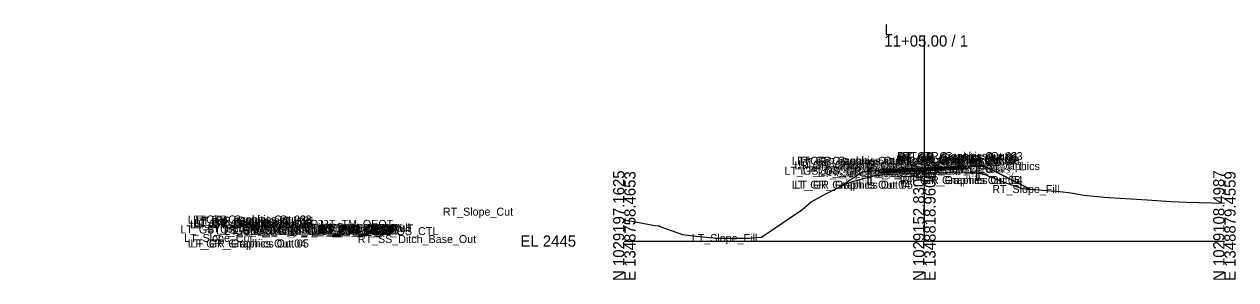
# Model space of a CAD drawing. Extents: x -26 to 1453, y -10 to 4527.
# Drawn here: x 1150 to 1452.8, y -9.7 to 54.3 of the extents above; entities that cross this region are included whole.
import ezdxf

# ---------------------------------------------------------------- set-up
doc = ezdxf.new("R2010")
doc.units = 0
for name, color, linetype in [('Default', 7, 'Continuous'), ('Exist Cross Section Cell', 7, 'Continuous'), ('Exist XS Center Line Elevation Label', 7, 'Continuous'), ('Exist XS Ground Line', 7, 'Continuous'), ('Old_Level_63', 7, 'Continuous'), ('Prop CMT Guardrail Graphics', 7, 'Continuous'), ('Prop CMT Pvmt Course 1', 7, 'Continuous'), ('Prop CMT Pvmt Course 2', 7, 'Continuous'), ('Prop CMT Pvmt Course 3', 7, 'Continuous'), ('Prop CMT Pvmt Surface', 7, 'Continuous'), ('Prop CMT Pvmt Surface Overlay', 7, 'Continuous'), ('Prop CMT Pvmt Surface Shoulder', 7, 'Continuous'), ('Prop CMT Shld Paved Course 1', 7, 'Continuous'), ('Prop CMT Shld Paved Course 2', 7, 'Continuous'), ('Prop CMT Shld Paved Course 3', 7, 'Continuous'), ('Prop CMT Slope Grass', 7, 'Continuous'), ('Prop CMT Subgrade Earthwork', 7, 'Continuous'), ('Prop XS Earthwork Shape', 7, 'Continuous'), ('Prop XS EOT Tick Mark', 7, 'Continuous'), ('Prop XS SE Text', 7, 'Continuous'), ('Prop XS Side Slope Text', 7, 'Continuous')]:
    doc.layers.add(name, color=color, linetype=linetype)

msp = doc.modelspace()

# ---------------------------------------------------------------- linework, layer by layer
at = {"layer": 'Exist Cross Section Cell'}
for p, q in [((1375, 0), (1375, 51.49)), ((1300, 0), (1375, 0)), ((1375, 0), (1450, 0))]:
    msp.add_line(p, q, dxfattribs=at)
at = {"layer": 'Exist XS Ground Line'}
msp.add_lwpolyline([(1300, 5.32), (1303.73, 4.67), (1307.54, 3.94), (1308.46, 3.79), (1308.77, 3.81), (1309.11, 3.59), (1314.51, 1.66), (1317.96, 1.27), (1323.09, 0.76), (1330.64, 0.75), (1334.29, 0.96), (1344.35, 7.82), (1346.72, 9.86), (1350.36, 11.85), (1354.94, 14.05), (1356.27, 14.69), (1357.04, 14.91), (1362.25, 16.35), (1365.44, 16.65), (1367.07, 16.77), (1368.72, 16.85), (1375, 17.08), (1376.08, 17.12), (1378.11, 17.11), (1385.47, 17.16), (1387.13, 17.06), (1389.45, 16.93), (1395.37, 14.58), (1399.46, 13.14), (1403.47, 12.8), (1408.88, 12.38), (1411.63, 12.09), (1414.85, 11.52), (1419.92, 10.98), (1430.69, 10.29), (1436.67, 9.87), (1440.4, 9.74), (1450, 9.5)], dxfattribs=at)
at = {"layer": 'Prop CMT Guardrail Graphics'}
for points in [[(1388.67, 21.27), (1387.34, 21.27), (1387.07, 20.98)], [(1388.67, 15.27), (1388.67, 21.27)], [(1360.98, 14.11), (1360.98, 20.11)], [(1360.98, 20.11), (1362.31, 20.11), (1362.58, 19.81)], [(1362.58, 19.23), (1362.31, 18.94), (1361.64, 18.94)], [(1361.64, 18.94), (1361.64, 14.11)], [(1362.58, 19.81), (1362.31, 19.52)], [(1362.31, 19.52), (1362.58, 19.23)], [(1387.07, 20.98), (1387.34, 20.69)], [(1387.34, 20.69), (1387.07, 20.4)], [(1387.07, 20.4), (1387.34, 20.11), (1388.01, 20.11)], [(1388.01, 20.11), (1388.01, 15.27)], [(1388.01, 15.27), (1388.67, 15.27)], [(1361.64, 14.11), (1360.98, 14.11)]]:
    msp.add_lwpolyline(points, dxfattribs=at)
at = {"layer": 'Prop CMT Pvmt Course 1'}
for points in [[(1374.96, 18.3), (1364.96, 17.8)], [(1374.96, 18.3), (1384.96, 18.8)], [(1384.96, 18.55), (1374.96, 18.05)], [(1374.96, 18.17), (1374.96, 18.3)], [(1374.96, 18.17), (1374.96, 18.3)], [(1384.96, 18.8), (1384.96, 18.55)], [(1364.96, 17.55), (1374.96, 18.05)], [(1364.96, 17.8), (1364.96, 17.55)], [(1374.96, 18.05), (1374.96, 18.17), (1374.96, 18.17)], [(1374.96, 18.05), (1374.96, 18.17), (1374.96, 18.17)]]:
    msp.add_lwpolyline(points, dxfattribs=at)
at = {"layer": 'Prop CMT Pvmt Course 2'}
for points in [[(1374.96, 18.05), (1384.96, 18.55)], [(1384.96, 18.3), (1374.96, 17.8)], [(1384.96, 18.55), (1384.96, 18.3)], [(1374.96, 18.05), (1364.96, 17.55)], [(1364.96, 17.3), (1374.96, 17.8)], [(1364.96, 17.55), (1364.96, 17.3)], [(1374.96, 17.8), (1374.96, 18.05)], [(1374.96, 17.8), (1374.96, 18.05)]]:
    msp.add_lwpolyline(points, dxfattribs=at)
at = {"layer": 'Prop CMT Pvmt Course 3'}
for points in [[(1374.96, 17.8), (1384.96, 18.3)], [(1384.96, 18.3), (1384.96, 18.05)], [(1374.96, 17.8), (1364.96, 17.3)], [(1364.96, 17.05), (1374.96, 17.55)], [(1364.96, 17.3), (1364.96, 17.05)], [(1384.96, 18.05), (1374.96, 17.55)], [(1374.96, 17.55), (1374.96, 17.8)], [(1374.96, 17.55), (1374.96, 17.8)]]:
    msp.add_lwpolyline(points, dxfattribs=at)
at = {"layer": 'Prop CMT Pvmt Surface'}
for points in [[(1374.96, 18.3), (1364.96, 17.8)], [(1374.96, 18.3), (1384.96, 18.8)]]:
    msp.add_lwpolyline(points, dxfattribs=at)
at = {"layer": 'Prop CMT Pvmt Surface Overlay'}
for points in [[(1374.96, 18.3), (1364.96, 17.8)], [(1374.96, 18.3), (1384.96, 18.8)]]:
    msp.add_lwpolyline(points, dxfattribs=at)
at = {"layer": 'Prop CMT Pvmt Surface Shoulder'}
for points in [[(1384.96, 18.8), (1384.96, 18.8)], [(1364.96, 17.8), (1364.96, 17.8)]]:
    msp.add_lwpolyline(points, dxfattribs=at)
at = {"layer": 'Prop CMT Shld Paved Course 1'}
for points in [[(1384.96, 18.8), (1384.96, 18.8), (1385.2, 18.56)], [(1384.96, 18.55), (1384.96, 18.8)], [(1385.2, 18.56), (1384.96, 18.55)], [(1364.96, 17.8), (1364.96, 17.8), (1364.7, 17.53)], [(1364.7, 17.53), (1364.96, 17.55)], [(1364.96, 17.55), (1364.96, 17.8)]]:
    msp.add_lwpolyline(points, dxfattribs=at)
at = {"layer": 'Prop CMT Shld Paved Course 2'}
for points in [[(1384.96, 18.55), (1385.2, 18.56), (1385.43, 18.32)], [(1384.96, 18.3), (1384.96, 18.55)], [(1385.43, 18.32), (1384.96, 18.3)], [(1364.96, 17.55), (1364.7, 17.53), (1364.43, 17.27)], [(1364.43, 17.27), (1364.96, 17.3)], [(1364.96, 17.3), (1364.96, 17.55)]]:
    msp.add_lwpolyline(points, dxfattribs=at)
at = {"layer": 'Prop CMT Shld Paved Course 3'}
for points in [[(1384.96, 18.3), (1385.43, 18.32)], [(1384.96, 18.05), (1384.96, 18.3)], [(1385.43, 18.32), (1385.43, 18.32)], [(1385.43, 18.32), (1385.67, 18.08)], [(1364.43, 17.27), (1364.17, 17.01)], [(1364.17, 17.01), (1364.96, 17.05)], [(1364.96, 17.3), (1364.43, 17.27)], [(1364.43, 17.27), (1364.43, 17.27)], [(1364.96, 17.05), (1364.96, 17.3)], [(1385.67, 18.08), (1384.96, 18.05)]]:
    msp.add_lwpolyline(points, dxfattribs=at)
at = {"layer": 'Prop CMT Slope Grass'}
for points in [[(1384.96, 18.8), (1387.07, 18.77)], [(1387.07, 18.77), (1390.07, 18.74)], [(1390.07, 18.74), (1401.65, 12.95)], [(1359.58, 17.37), (1353.75, 13.48)], [(1362.58, 17.61), (1359.58, 17.37)], [(1364.96, 17.8), (1362.58, 17.61)]]:
    msp.add_lwpolyline(points, dxfattribs=at)
at = {"layer": 'Prop CMT Subgrade Earthwork'}
for points in [[(1385.67, 18.08), (1386.37, 18.78)], [(1364.17, 17.01), (1363.5, 17.68)], [(1364.96, 17.05), (1364.17, 17.01)], [(1374.96, 17.55), (1364.96, 17.05)], [(1374.96, 17.55), (1384.96, 18.05)], [(1384.96, 18.05), (1385.67, 18.08)]]:
    msp.add_lwpolyline(points, dxfattribs=at)
at = {"layer": 'Prop XS Earthwork Shape'}
for points in [[(1399.46, 13.14), (1401.65, 12.95), (1390.07, 18.74), (1387.07, 18.77), (1386.37, 18.78), (1385.67, 18.08), (1384.96, 18.05), (1374.96, 17.55), (1364.96, 17.05), (1364.17, 17.01), (1363.5, 17.68), (1362.58, 17.61), (1359.58, 17.37), (1353.75, 13.48), (1354.94, 14.05), (1356.27, 14.69), (1357.04, 14.91), (1362.25, 16.35), (1365.44, 16.65), (1367.07, 16.77), (1368.72, 16.85), (1375, 17.08), (1376.08, 17.12), (1378.11, 17.11), (1385.47, 17.16), (1387.13, 17.06), (1389.45, 16.93), (1395.37, 14.58)], [(1362.58, 17.61), (1359.58, 17.37), (1353.75, 13.48), (1354.94, 14.05), (1356.27, 14.69), (1357.04, 14.91), (1362.25, 16.35), (1365.44, 16.65), (1367.07, 16.77), (1368.72, 16.85), (1375, 17.08), (1376.08, 17.12), (1378.11, 17.11), (1385.47, 17.16), (1387.13, 17.06), (1389.45, 16.93), (1395.37, 14.58), (1399.46, 13.14), (1401.65, 12.95), (1390.07, 18.74), (1387.07, 18.77), (1386.37, 18.78), (1385.67, 18.08), (1384.96, 18.05), (1374.96, 17.55), (1364.96, 17.05), (1364.17, 17.01), (1363.5, 17.68)]]:
    msp.add_lwpolyline(points, close=True, dxfattribs=at)
at = {"layer": 'Prop XS EOT Tick Mark'}
for points in [[(1364.96, 17.8), (1364.96, 18.8)], [(1384.96, 18.8), (1384.96, 19.8)]]:
    msp.add_lwpolyline(points, dxfattribs=at)

# ---------------------------------------------------------------- texts
at = {"layer": 'Default'}
for s, height, p in [('LT_GR_Graphics Out 03', 2, (1190.88, 4.4)), ('LT_GR_Graphics Out 02', 2, (1192.21, 4.4)), ('LT_GR_Graphics Out 01', 2, (1193.05, 4.11)), ('RT_Slope_Cut', 2, (1254.65, 6.36)), ('LT_GS_OS_GR_Face_Graphics', 2, (1189.04, 1.9)), ('LT_GR_Graphics Out 06', 2, (1191.5, 3.23)), ('LT_GR_Graphics Out 09', 2, (1192.21, 3.82)), ('LT_GR_Graphics Out 07', 2, (1192.21, 3.23)), ('LT_GR_Graphics Out 08', 2, (1192.48, 3.52)), ('LT_Sub_Trench_Out_DLT', 2, (1195.78, 2.19)), ('LT_GS_OS_CTL', 2, (1197.96, 1.66)), ('LT_Sub_Trench_Out', 2, (1200.07, 1.54)), ('LT_PV_Sub_Tie_Out', 2, (1202.08, 2.18)), ('LT_PS3_Shelf_Out', 2, (1202.11, 1.79)), ('LT_PV_EG_TestPt3', 2, (1203.52, 2.19)), ('LT_PV1_OEEOP_Null', 2, (1203.59, 2.31)), ('LT_PV_OEEOP_EG', 2, (1204.68, 2.18)), ('LT_PV1_OEEOP_W', 2, (1205.12, 2.19)), ('LT_Sub_OEEOP', 2, (1206.35, 1.56)), ('LT_PS3_OEOP', 2, (1206.36, 1.79)), ('LT_PV2_OEEOP', 2, (1206.44, 2.06)), ('LT_PV3_OEEOP', 2, (1206.44, 1.81)), ('LT_PV_EG_TestPt2', 2, (1206.58, 2.24)), ('LT_PS2_OEOP', 2, (1206.61, 2.05)), ('LT_Sub_OEOT', 2, (1206.71, 1.55)), ('LT_PV2_OEOT', 2, (1206.81, 2.05)), ('LT_PV3_OEOT', 2, (1206.81, 1.8)), ('LT_PV1_OEOT', 2, (1207.37, 2.3)), ('LT_PS1_OEOP', 2, (1207.44, 2.3)), ('LT_TM_OEOT', 2, (1207.58, 3.3)), ('LT_PV_EG_TestPt1', 2, (1210.21, 2.29)), ('RT_PV_EG_TestPt1', 2, (1211.9, 2.3)), ('RT_PV_EG_TestPt2', 2, (1214.39, 2.25)), ('RT_Sub_Trench_Out_DLT', 2, (1215.29, 2.19)), ('PV_EPGL_EG', 2, (1216.24, 2.3)), ('PV2_PGL_W', 2, (1217.02, 2.22)), ('PV3_PGL_W', 2, (1217.02, 1.97)), ('RT_PV_EG_TestPt3', 2, (1217.44, 2.2)), ('PV1_PGL_W', 2, (1217.58, 2.34)), ('RT_PV_Sub_Tie_Out', 2, (1217.75, 2.19)), ('RT_Sub_Trench_Out', 2, (1218.28, 1.54)), ('RT_PV1_OEEOP_Null', 2, (1219.26, 2.31)), ('PV1_PGL', 2, (1219.47, 2.47)), ('RT_PS3_Shelf_Out', 2, (1219.8, 1.79)), ('RT_PV_OEEOP_EG', 2, (1220.35, 2.19)), ('RT_PV1_OEEOP_W', 2, (1220.79, 2.19)), ('RT_Sub_OEEOP', 2, (1222.02, 1.56)), ('RT_PV2_OEEOP', 2, (1222.11, 2.06)), ('RT_PV3_OEEOP', 2, (1222.11, 1.81)), ('RT_Sub_OEOT', 2, (1223.38, 1.55)), ('RT_PV2_OEOT', 2, (1223.48, 2.05)), ('RT_PV3_OEOT', 2, (1223.48, 1.8)), ('RT_PS2_OEOP', 2, (1223.8, 2.05)), ('RT_PV1_OEOT', 2, (1224.05, 2.3)), ('RT_PS3_OEOP', 2, (1224.05, 1.79)), ('RT_PS1_OEOP', 2, (1224.11, 2.3)), ('RT_TM_OEOT', 2, (1224.25, 3.3)), ('RT_GS_OS_CTL', 2, (1232.68, 1.5)), ('-', 0.0001, (1150, 0)), ('LT_Slope_Cut', 2, (1189.97, -0.21)), ('LT_GR_Graphics Out 04', 2, (1190.88, -1.6)), ('LT_GR_Graphics Out 05', 2, (1191.55, -1.6)), ('RT_SS_Ditch_Base_Out', 2, (1233.38, -0.5)), ('-', 0.0001, (1300, 0))]:
    msp.add_text(s, height=height, dxfattribs=at).set_placement(p)
at = {"layer": 'Exist Cross Section Cell'}
for s, p in [('11+05.00 / 1', (1365, 48.69)), ('L', (1365, 51.49)), ('EL 2445', (1274, -1.4))]:
    msp.add_text(s, height=2.8, dxfattribs=at).set_placement(p)
for s, p in [('N 1029197.1625', (1300, -10)), ('E 1348758.4653', (1302.8, -10)), ('N 1029152.8306', (1375, -10)), ('E 1348818.9606', (1377.8, -10)), ('N 1029108.4987', (1450, -10)), ('E 1348879.4559', (1452.8, -10))]:
    msp.add_text(s, height=2.8, rotation=90, dxfattribs=at).set_placement(p)
at = {"layer": 'Exist XS Center Line Elevation Label'}
msp.add_text('2462.08', height=1.23, dxfattribs=at).set_placement((1371.88, 15.35))
at = {"layer": 'Old_Level_63'}
for s, p in [('LT_GR_Graphics Out 03', (1341.87, 19.11)), ('LT_GR_Graphics Out 02', (1343.21, 19.11)), ('RT_GR_Graphics Out 08', (1367.92, 19.4)), ('RT_GR_Graphics Out 02', (1368.19, 20.27)), ('RT_GR_Graphics Out 09', (1368.19, 19.69)), ('RT_GR_Graphics Out 07', (1368.19, 19.11)), ('RT_GR_Graphics Out 01', (1368.49, 19.98)), ('RT_GR_Graphics Out 06', (1368.81, 19.11)), ('RT_GR_Graphics Out 03', (1369.52, 20.27)), ('LT_GS_OS_GR_Face_Graphics', (1340.04, 16.61)), ('LT_GR_Graphics Out 06', (1342.49, 17.94)), ('LT_GR_Graphics Out 09', (1343.21, 18.52)), ('LT_GR_Graphics Out 07', (1343.21, 17.94)), ('LT_GR_Graphics Out 08', (1343.48, 18.23)), ('LT_GR_Graphics Out 01', (1344.05, 18.81)), ('LT_Sub_Trench_Out_DLT', (1344.06, 16.68)), ('LT_GS_OS_CTL', (1348.95, 16.37)), ('LT_PS3_Shelf_Out', (1350.42, 16.27)), ('LT_PS3_OEOP', (1354.67, 16.27)), ('LT_PS2_OEOP', (1354.93, 16.53)), ('LT_PV2_OEOT', (1355.13, 16.55)), ('LT_PV3_OEOT', (1355.13, 16.3)), ('LT_PV1_OEOT', (1355.7, 16.8)), ('LT_PS1_OEOP', (1355.76, 16.8)), ('LT_TM_OEOT', (1355.9, 17.8)), ('RT_PV1_OEEOP_W', (1362.9, 17.17)), ('LT_PV1_OEEOP_W', (1362.94, 17.17)), ('RT_Sub_OEEOP', (1364.12, 16.55)), ('LT_Sub_OEEOP', (1364.17, 16.55)), ('RT_PV2_OEEOP', (1364.22, 17.05)), ('RT_PV3_OEEOP', (1364.22, 16.8)), ('LT_PV2_OEEOP', (1364.27, 17.05)), ('LT_PV3_OEEOP', (1364.27, 16.8)), ('RT_GS_OS_GR_Face_Graphics', (1364.48, 17.77)), ('RT_Sub_Trench_Out_DLT', (1366.89, 17.78)), ('PV1_PGL_W', (1367.54, 17.17)), ('PV1_PGL', (1369.43, 17.3)), ('RT_Sub_Trench_Out', (1369.83, 17.08)), ('RT_PS3_Shelf_Out', (1371.37, 17.32)), ('RT_Sub_OEOT', (1374.99, 17.05)), ('RT_PV2_OEOT', (1375.08, 17.55)), ('RT_PV3_OEOT', (1375.08, 17.3)), ('RT_PS2_OEOP', (1375.38, 17.56)), ('RT_PS3_OEOP', (1375.62, 17.32)), ('RT_PV1_OEOT', (1375.65, 17.8)), ('RT_PS1_OEOP', (1375.71, 17.8)), ('RT_TM_OEOT', (1375.85, 18.8)), ('RT_GS_OS_CTL', (1379.39, 17.74)), ('LT_GR_Graphics Out 04', (1341.87, 13.11)), ('LT_GR_Graphics Out 05', (1342.54, 13.11)), ('LT_Sub_Trench_Out', (1348.37, 16.01)), ('LT_Sub_OEOT', (1355.04, 16.05)), ('RT_GR_Graphics Out 05', (1368.86, 14.27)), ('RT_GR_Graphics Out 04', (1369.52, 14.27)), ('RT_Slope_Fill', (1391.98, 12.02)), ('LT_Slope_Fill', (1316.88, -0.25))]:
    msp.add_text(s, height=2, dxfattribs=at).set_placement(p)
at = {"layer": 'Prop XS SE Text'}
for p in [(1368.16, 18.96), (1378.16, 19.46)]:
    msp.add_text('0.050', height=1, rotation=2.8628, dxfattribs=at).set_placement(p)
at = {"layer": 'Prop XS Side Slope Text'}
for s, rotation, p in [('1.5:1', 33.6901, (1355.39, 15.03)), ('2:1', 333.4321, (1395.42, 16.91))]:
    msp.add_text(s, height=1, rotation=rotation, dxfattribs=at).set_placement(p)

doc.saveas('drawing.dxf')
